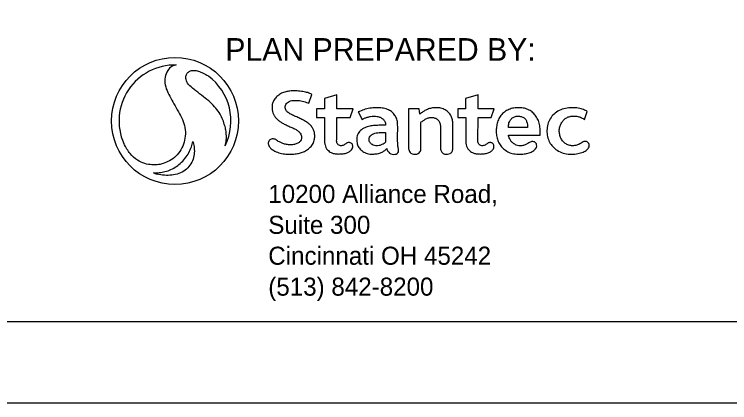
# Model space of a CAD drawing. Extents: x 0 to 45, y -99 to 22.
# Drawn here: x 2.904 to 7.34, y 0 to 2.407 of the extents above; entities that cross this region are included whole.
import ezdxf

# ---------------------------------------------------------------- set-up
doc = ezdxf.new("R2010")
doc.units = 0
for name, color, linetype in [('SH_Border', 7, 'Continuous'), ('SH_Data', 7, 'Continuous'), ('SH_Text', 7, 'Continuous')]:
    doc.layers.add(name, color=color, linetype=linetype)

msp = doc.modelspace()

# ---------------------------------------------------------------- linework, layer by layer
at = {"layer": 'SH_Border'}
msp.add_lwpolyline([(1.5, 21.5), (33.5, 21.5), (33.5, 0.5), (1.5, 0.5)], close=True, dxfattribs=at)
at = {"layer": 'SH_Data'}
msp.add_lwpolyline([(0, 0), (34, 0), (34, 22), (0, 22)], close=True, dxfattribs=at)
at = {"layer": 'SH_Text'}
for p, q in [((4.7306, 1.8556), (4.7499, 1.9104)), ((4.9045, 1.9071), (4.827, 1.8855)), ((4.827, 1.8855), (4.827, 1.8211)), ((4.9045, 1.821), (4.9045, 1.9071)), ((5.7803, 1.9071), (5.7028, 1.8855)), ((5.7028, 1.8855), (5.7028, 1.8211)), ((5.7803, 1.821), (5.7803, 1.9071)), ((4.827, 1.8211), (4.7778, 1.8211)), ((4.7778, 1.8211), (4.7778, 1.7671)), ((5.0047, 1.821), (4.9045, 1.821)), ((4.986, 1.7671), (5.0047, 1.821)), ((5.4141, 1.8209), (5.3489, 1.8209)), ((5.3489, 1.8209), (5.3489, 1.5737)), ((5.4185, 1.7881), (5.4141, 1.8209)), ((5.7028, 1.8211), (5.6535, 1.8211)), ((5.6535, 1.8211), (5.6535, 1.7671)), ((5.8805, 1.821), (5.7803, 1.821)), ((5.8618, 1.7671), (5.8805, 1.821)), ((5.0371, 1.8013), (5.0607, 1.7557)), ((6.4397, 1.754), (6.4569, 1.8046)), ((4.7778, 1.7671), (4.8275, 1.7671)), ((4.903, 1.6309), (4.904, 1.7671)), ((4.904, 1.7671), (4.986, 1.7671)), ((5.4248, 1.5737), (5.4248, 1.7368)), ((5.6535, 1.7671), (5.7033, 1.7671)), ((5.7787, 1.6309), (5.7798, 1.7671)), ((5.7798, 1.7671), (5.8618, 1.7671)), ((6.0868, 1.7057), (5.9686, 1.7058)), ((5.2064, 1.6746), (5.2064, 1.6134)), ((5.9686, 1.6583), (6.1653, 1.6583))]:
    msp.add_line(p, q, dxfattribs=at)
for points in [[(3.908, 2.0926), (3.908, 2.0926)], [(4.1073, 2.0244), (4.1073, 2.0243)]]:
    msp.add_lwpolyline(points, dxfattribs=at)
msp.add_circle((3.9005, 1.7456), 0.3937, dxfattribs=at)
for start, end in [(88.7666, 203.6845), (88.7601, 88.7666), (333.7815, 53.4326), (247.1184, 251.458)]:
    msp.add_arc((3.9005, 1.7456), 0.347, start, end, dxfattribs=at)
for points, degree in [([(3.908, 2.0926), (3.8996, 2.0908), (3.8799, 2.0866), (3.8541, 2.0603), (3.835, 2.0172), (3.8375, 1.9687), (3.8546, 1.9219), (3.8805, 1.8764), (3.9073, 1.8261), (3.937, 1.7787), (3.9576, 1.7306), (3.9674, 1.6782), (3.9609, 1.6257), (3.9457, 1.5775), (3.9161, 1.5338), (3.8772, 1.5028), (3.8365, 1.4846), (3.7997, 1.4731), (3.7586, 1.4731), (3.7129, 1.4796), (3.6679, 1.5002), (3.6199, 1.5408), (3.5968, 1.5808), (3.5827, 1.6062)], 3), ([(3.908, 2.0926), (3.908, 2.0926), (3.908, 2.0926), (3.908, 2.0926)], 2), ([(4.2118, 1.5923), (4.2149, 1.6045), (4.22, 1.6273), (4.2191, 1.664), (4.2155, 1.6962), (4.206, 1.7261), (4.1949, 1.7607), (4.1753, 1.7983), (4.1473, 1.8337), (4.1108, 1.8709), (4.0652, 1.9041), (4.0182, 1.9425), (3.9805, 1.9708), (3.9672, 2.0041), (3.9671, 2.0294), (3.9795, 2.0465), (3.9963, 2.0585), (4.0184, 2.0604), (4.0446, 2.0554), (4.075, 2.0426), (4.0959, 2.0308), (4.1073, 2.0244)], 3), ([(4.7499, 1.9104), (4.7465, 1.9121), (4.7312, 1.9194), (4.7019, 1.9271), (4.6661, 1.9315), (4.6336, 1.9331), (4.6064, 1.9305), (4.5804, 1.9251), (4.5554, 1.9151), (4.5312, 1.8986), (4.5138, 1.8764), (4.5041, 1.854), (4.5018, 1.8331), (4.5028, 1.8139), (4.5069, 1.7955), (4.5147, 1.7803), (4.5241, 1.7665), (4.5358, 1.7541), (4.5499, 1.7428), (4.5674, 1.7322), (4.5889, 1.7211), (4.6128, 1.7102), (4.6371, 1.6998), (4.6572, 1.6895), (4.6719, 1.677), (4.6821, 1.6652), (4.6856, 1.6507), (4.6851, 1.6371), (4.6796, 1.622), (4.667, 1.6095), (4.6471, 1.6008), (4.6235, 1.5974), (4.5974, 1.5986), (4.5742, 1.6033), (4.5556, 1.6127), (4.5404, 1.6189), (4.5302, 1.6284), (4.5205, 1.6321), (4.5116, 1.636), (4.5021, 1.6353), (4.4925, 1.6324), (4.4844, 1.6254), (4.479, 1.6153), (4.4786, 1.6043), (4.4803, 1.5935), (4.4888, 1.5819), (4.5053, 1.5655), (4.5345, 1.5511), (4.5706, 1.5415), (4.6071, 1.5396), (4.6387, 1.5405), (4.6662, 1.544), (4.6904, 1.5513), (4.7155, 1.5627), (4.7398, 1.5817), (4.7585, 1.6053), (4.7664, 1.6331), (4.7675, 1.6582), (4.7644, 1.6809), (4.7555, 1.6991), (4.7446, 1.7173), (4.7258, 1.7328), (4.7044, 1.7471), (4.6808, 1.7584), (4.6554, 1.7704), (4.6289, 1.7818), (4.6063, 1.7937), (4.5911, 1.8074), (4.5847, 1.8207), (4.5835, 1.8348), (4.5877, 1.8475), (4.5963, 1.8587), (4.6084, 1.8667), (4.6243, 1.8725), (4.6434, 1.8739), (4.6622, 1.8731), (4.6809, 1.8702), (4.6989, 1.8663), (4.7159, 1.8612), (4.7261, 1.8573), (4.7306, 1.8556)], 3), ([(5.2139, 1.5751), (5.2141, 1.5725), (5.2147, 1.5661), (5.2211, 1.5566), (5.2301, 1.5461), (5.2466, 1.5383), (5.264, 1.5389), (5.2803, 1.5425), (5.2865, 1.5552), (5.2868, 1.5681), (5.2832, 1.5854), (5.2792, 1.6328), (5.2822, 1.6829), (5.2813, 1.737), (5.2751, 1.7632), (5.2604, 1.7869), (5.2444, 1.8049), (5.2183, 1.8182), (5.1859, 1.8266), (5.1474, 1.8291), (5.1086, 1.8253), (5.0711, 1.8166), (5.0481, 1.8063), (5.0371, 1.8013)], 3), ([(5.4248, 1.7368), (5.4261, 1.738), (5.4314, 1.7428), (5.4441, 1.7506), (5.4605, 1.7615), (5.4814, 1.7678), (5.5026, 1.7676), (5.5231, 1.761), (5.5372, 1.7464), (5.5448, 1.729), (5.5487, 1.7055), (5.5462, 1.6703), (5.548, 1.6256), (5.5457, 1.5885), (5.5473, 1.5627), (5.5561, 1.549), (5.5716, 1.5392), (5.5894, 1.5395), (5.6066, 1.5436), (5.6205, 1.5542), (5.6246, 1.5746), (5.6216, 1.6105), (5.6235, 1.6547), (5.6225, 1.7033), (5.6243, 1.7342), (5.6201, 1.761), (5.6118, 1.7799), (5.5984, 1.7991), (5.5768, 1.8143), (5.5498, 1.8271), (5.5188, 1.8279), (5.491, 1.8263), (5.466, 1.818), (5.4438, 1.8077), (5.4289, 1.796), (5.421, 1.79), (5.4185, 1.7881)], 3), ([(6.1653, 1.6583), (6.1656, 1.6658), (6.1663, 1.6847), (6.1629, 1.7149), (6.1552, 1.749), (6.1389, 1.7752), (6.1204, 1.798), (6.097, 1.814), (6.0673, 1.8258), (6.034, 1.8279), (6.0012, 1.8273), (5.9702, 1.8175), (5.9436, 1.8023), (5.9204, 1.7803), (5.9047, 1.7536), (5.8959, 1.7243), (5.8925, 1.6944), (5.8921, 1.6622), (5.8992, 1.6324), (5.911, 1.6033), (5.9289, 1.5785), (5.9563, 1.5588), (5.9904, 1.5419), (6.03, 1.5398), (6.066, 1.5403), (6.0967, 1.5468), (6.1208, 1.5585), (6.1385, 1.5737), (6.1448, 1.5903), (6.1419, 1.6037), (6.1353, 1.6144), (6.1247, 1.6174), (6.1143, 1.6187), (6.1022, 1.615), (6.0879, 1.6061), (6.0715, 1.5961), (6.0515, 1.5916), (6.033, 1.5911), (6.0147, 1.5958), (5.9995, 1.6063), (5.9845, 1.6186), (5.9757, 1.635), (5.9702, 1.6484), (5.969, 1.6558), (5.9686, 1.6583)], 3), ([(6.4569, 1.8046), (6.4503, 1.8083), (6.4342, 1.8173), (6.4027, 1.8255), (6.3636, 1.8296), (6.3219, 1.8248), (6.2821, 1.8118), (6.2492, 1.7898), (6.2255, 1.76), (6.2107, 1.7256), (6.2055, 1.6869), (6.2086, 1.648), (6.2218, 1.613), (6.2416, 1.5862), (6.269, 1.5628), (6.3066, 1.5453), (6.3506, 1.5383), (6.3909, 1.541), (6.4243, 1.5498), (6.4508, 1.562), (6.4679, 1.5785), (6.4689, 1.5943), (6.4674, 1.6061), (6.4595, 1.6133), (6.4514, 1.6182), (6.4424, 1.6188), (6.4303, 1.6168), (6.4195, 1.6074), (6.4038, 1.6008), (6.3881, 1.5934), (6.3657, 1.5917), (6.3422, 1.5938), (6.3197, 1.6061), (6.3028, 1.623), (6.2891, 1.6435), (6.2851, 1.6676), (6.2816, 1.6914), (6.2884, 1.715), (6.2975, 1.7366), (6.3109, 1.7538), (6.329, 1.7667), (6.3496, 1.7747), (6.3738, 1.7767), (6.3979, 1.7744), (6.4211, 1.7671), (6.4337, 1.7582), (6.4397, 1.754)], 3), ([(5.0607, 1.7557), (5.0642, 1.7576), (5.075, 1.7633), (5.0925, 1.7687), (5.1136, 1.7741), (5.1338, 1.7756), (5.1547, 1.7747), (5.1734, 1.7689), (5.1898, 1.7595), (5.2013, 1.7457), (5.2062, 1.7318), (5.2062, 1.7231), (5.2062, 1.7202)], 3), ([(5.9686, 1.7058), (5.9686, 1.7082), (5.9686, 1.7143), (5.9694, 1.7258), (5.9732, 1.7406), (5.9824, 1.7562), (5.9967, 1.7688), (6.0163, 1.7757), (6.0373, 1.7762), (6.0569, 1.7703), (6.0735, 1.7596), (6.0818, 1.7414), (6.0859, 1.7233), (6.0865, 1.7112), (6.0868, 1.7057)], 3), ([(4.8275, 1.7671), (4.8273, 1.7189), (4.8271, 1.6681), (4.8276, 1.6115), (4.8302, 1.5979), (4.8355, 1.5793), (4.846, 1.5668), (4.8567, 1.5569), (4.868, 1.5494), (4.886, 1.5431), (4.9108, 1.5404), (4.9364, 1.5414), (4.9619, 1.545), (4.9814, 1.5549), (4.9957, 1.5665), (5.0024, 1.5797), (5.0031, 1.5913), (5.001, 1.6011), (4.9958, 1.6069), (4.9897, 1.6105), (4.9824, 1.6118), (4.9748, 1.612), (4.967, 1.61), (4.9601, 1.6045), (4.9523, 1.5986), (4.9427, 1.5944), (4.9325, 1.5911), (4.922, 1.5923), (4.9128, 1.5973), (4.9057, 1.6044), (4.9027, 1.6166), (4.9029, 1.6253), (4.903, 1.6309)], 3), ([(5.7033, 1.7671), (5.7031, 1.7189), (5.7028, 1.6681), (5.7034, 1.6115), (5.7059, 1.5979), (5.7113, 1.5793), (5.7218, 1.5668), (5.7325, 1.5569), (5.7438, 1.5494), (5.7618, 1.5431), (5.7866, 1.5404), (5.8121, 1.5414), (5.8377, 1.545), (5.8572, 1.5549), (5.8715, 1.5665), (5.8781, 1.5797), (5.8789, 1.5913), (5.8767, 1.6011), (5.8716, 1.6069), (5.8655, 1.6105), (5.8582, 1.6118), (5.8505, 1.612), (5.8428, 1.61), (5.8358, 1.6045), (5.828, 1.5986), (5.8184, 1.5944), (5.8082, 1.5911), (5.7977, 1.5923), (5.7886, 1.5973), (5.7815, 1.6044), (5.7785, 1.6166), (5.7786, 1.6253), (5.7787, 1.6309)], 3), ([(5.2062, 1.7202), (5.2012, 1.7201), (5.1849, 1.7198), (5.1568, 1.7185), (5.1235, 1.7168), (5.0922, 1.7098), (5.0633, 1.6979), (5.0382, 1.6762), (5.0264, 1.6456), (5.028, 1.6168), (5.0326, 1.592), (5.0477, 1.5711), (5.0696, 1.552), (5.1007, 1.5403), (5.1331, 1.5398), (5.1631, 1.5437), (5.1859, 1.5517), (5.2029, 1.5633), (5.2099, 1.5709), (5.2139, 1.5751)], 3), ([(5.2064, 1.6134), (5.2045, 1.6119), (5.1973, 1.6064), (5.1842, 1.5993), (5.1658, 1.5918), (5.1463, 1.5905), (5.1293, 1.595), (5.1175, 1.6026), (5.1098, 1.6116), (5.1048, 1.6225), (5.104, 1.6342), (5.1062, 1.6458), (5.1131, 1.6568), (5.125, 1.6639), (5.1392, 1.6702), (5.1579, 1.6727), (5.1771, 1.6738), (5.1939, 1.6748), (5.2028, 1.6747), (5.2064, 1.6746)], 3), ([(3.7656, 1.4259), (3.7741, 1.425), (3.7942, 1.423), (3.8286, 1.4297), (3.867, 1.4387), (3.9015, 1.4588), (3.9334, 1.4812), (3.9633, 1.5133), (3.9881, 1.549), (4.0038, 1.5862), (4.0086, 1.6081), (4.0109, 1.6186)], 3), ([(4.0109, 1.6186), (4.0134, 1.6098), (4.0199, 1.5872), (4.0215, 1.5495), (4.0151, 1.5087), (3.994, 1.4716), (3.9656, 1.4374), (3.9244, 1.4186), (3.8807, 1.4087), (3.8357, 1.4079), (3.8048, 1.4138), (3.7901, 1.4166)], 3), ([(5.3489, 1.5737), (5.3496, 1.5704), (5.3512, 1.5632), (5.3566, 1.5506), (5.3705, 1.54), (5.3898, 1.5399), (5.4092, 1.5413), (5.4208, 1.554), (5.4249, 1.5651), (5.4248, 1.5711), (5.4248, 1.5737)], 3)]:
    msp.add_open_spline(points, degree=degree, dxfattribs=at)

# ---------------------------------------------------------------- texts
for s, height, p in [('PLAN PREPARED BY:', 0.14, (4.2125, 2.119)), ('10200 Alliance Road, ', 0.112, (4.4789, 1.2378)), ('Suite 300', 0.112, (4.4789, 1.0463)), ('Cincinnati OH 45242', 0.112, (4.4789, 0.8547)), ('(513) 842-8200', 0.112, (4.4789, 0.6631))]:
    msp.add_text(s, height=height, dxfattribs=at).set_placement(p)

doc.saveas('drawing.dxf')
